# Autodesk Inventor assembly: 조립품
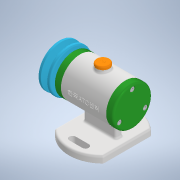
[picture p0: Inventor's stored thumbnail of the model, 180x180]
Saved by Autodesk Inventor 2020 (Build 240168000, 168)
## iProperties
Created: 2021-09
Part Number: 조립품
Document SubType Name: Weldment
Designer: Administrator
Weld Material: Welded Aluminum-6061
Author: Administrator
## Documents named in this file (14)
- C:\Users\Administrator\Desktop\710906V1022\조립품.iam
- C:\Users\Administrator\Desktop\710906V1022\본체.ipt
- C:\Users\Administrator\Desktop\710906V1022\축.ipt
- C:\Users\Administrator\Desktop\710906V1022\베어링 15x32x9.ipt
- C:\Users\Administrator\Desktop\710906V1022\뒤커버.ipt
- C:\Users\Administrator\Desktop\710906V1022\볼트 M4x12.ipt
- C:\Users\Administrator\Desktop\710906V1022\캡.ipt
- C:\Users\Administrator\Desktop\710906V1022\앞커버.ipt
- C:\Users\Administrator\Desktop\710906V1022\키 3x3.ipt
- C:\Users\Administrator\Desktop\710906V1022\오일 실 15x25x7.ipt
- C:\Users\Administrator\Desktop\710906V1022\V벨트풀리.ipt
- C:\Users\Administrator\Desktop\710906V1022\와셔 8x17.ipt
- C:\Users\Administrator\Desktop\710906V1022\스프링와셔 8.ipt
- C:\Users\Administrator\Desktop\710906V1022\너트 M8.ipt
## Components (1 placed, 1 different names)
1. V벨트풀리:1
